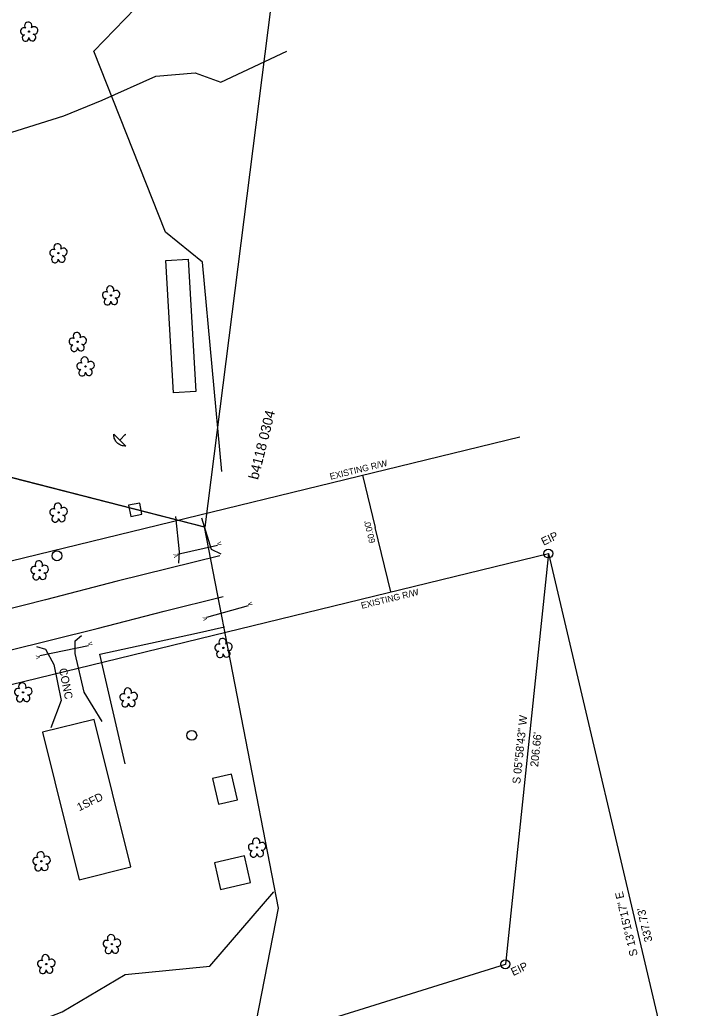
# Model space of a CAD drawing. Extents: x 1380524 to 1382335, y 594765 to 596944.
# Drawn here: x 1381991.4 to 1382333.2, y 595723.8 to 596218 of the extents above; entities that cross this region are included whole.
import ezdxf

# ---------------------------------------------------------------- set-up
doc = ezdxf.new("R2010")
doc.units = 0
for name, color, linetype in [('DTM Contours Major Text', 7, 'Continuous'), ('DTM Contours Minor', 7, 'Continuous'), ('Exist Other Culture Fence Line Text', 7, 'Continuous'), ('Exist Right of Way Line Text', 7, 'Continuous'), ('Exist Roads EOP', 7, 'Continuous'), ('Exist Structure Major Deck Tunnel Box Culvert', 7, 'Continuous'), ('Exist Utilities Power Tower CELL', 7, 'Continuous'), ('Exist Utilities Power Tower Text', 7, 'Continuous'), ('Exist Vertical Profile Vertical Axis Label', 7, 'Continuous'), ('Prop Approach Slab', 7, 'Continuous'), ('Prop Drainage Ditch Base Lines', 7, 'Continuous'), ('Prop Drainage Structure Box Number Symbol CELL', 7, 'Continuous'), ('Prop Drainage Structure Pipe CSP 15in', 7, 'Continuous'), ('Prop Drainage Structure Pipe Elbow CELL', 7, 'Continuous'), ('Prop Drainage Structure Pipe Elbow Label', 7, 'Continuous'), ('Prop Drainage Structure Plot Symbol 20 Scale CELL', 7, 'Continuous'), ('Prop Earthen Structure Cut Ditch Special Detail Label', 7, 'Continuous'), ('Prop Earthen Structure Ditch Flow Line', 7, 'Continuous'), ('Prop Earthen Structure V Ditch Lateral Detail Label', 7, 'Continuous'), ('Prop Erosion Rip Rap At Embankment Detail CELL', 7, 'Continuous'), ('Prop SS Transition Line', 7, 'Continuous')]:
    doc.layers.add(name, color=color, linetype=linetype)

# ---------------------------------------------------------------- blocks, each defined once
blk = doc.blocks.new('EXIST UTILITIES TV SATELLITE DISH')
at = {"layer": 'DTM Contours Minor'}
blk.add_line((0, 0), (0, 0), dxfattribs=at)
for points in [[(0.0605, -0.0604), (0.05, -0.0604), (0.0392, -0.0594), (0.0287, -0.0577), (0.0185, -0.0547), (0.0085, -0.0509), (-0.001, -0.0462), (-0.01, -0.0407), (-0.0185, -0.0344), (-0.0265, -0.0274), (-0.0335, -0.0194), (-0.0398, -0.0109), (-0.0453, -0.0019), (-0.05, 0.0076), (-0.0538, 0.0176), (-0.0568, 0.0278), (-0.0585, 0.0383), (-0.0595, 0.0491), (-0.0595, 0.0596)], [(-0.0595, 0.0596), (0.0605, -0.0604)], [(0, 0), (0.0585, 0.0575), (0.0578, 0.0585), (0.052, 0.0527), (0.0537, 0.051), (0.0595, 0.0568), (0.0585, 0.0575)]]:
    blk.add_lwpolyline(points, dxfattribs=at)
blk = doc.blocks.new('EXIST VEGETATION TREE')
at = {"layer": 'Prop Erosion Rip Rap At Embankment Detail CELL'}
blk.add_line((0, 0), (0, 0), dxfattribs=at)
blk.add_circle((0, 0), 0.00652, dxfattribs=at)
for centre, radius, start, end in [((-0.0521, 0.0031), 0.0345, 62.66361, 279.3457), ((-0.0077, 0.0575), 0.0371, 330.16508, 219.71335), ((0.051, 0.0118), 0.038, 257.1011, 134.19993), ((-0.0341, -0.0624), 0.0338, 111.56708, 6.23104), ((0.0335, -0.058), 0.034, 181.28216, 74.55999)]:
    blk.add_arc(centre, radius, start, end, dxfattribs=at)
blk = doc.blocks.new('EXIST UTILITIES OTHER POLE')
at = {"layer": 'DTM Contours Major Text'}
blk.add_circle((0, 0), 0.0493, dxfattribs=at)

msp = doc.modelspace()

# ---------------------------------------------------------------- linework, layer by layer
at = {"layer": 'Exist Roads EOP'}
for p, q in [((1381864.07, 595917.48), (1382241.54, 596009.42)), ((1381884.86, 595860.79), (1382255.74, 595951.12))]:
    msp.add_line(p, q, dxfattribs=at)
at = {"layer": 'Exist Utilities Power Tower CELL'}
for p in [(1382162.74, 595990.23), (1382176.94, 595931.93)]:
    msp.add_line(p, (1382169.1, 595964.11), dxfattribs=at)
at = {"layer": 'Exist Utilities Power Tower Text'}
for p, q in [((1382255.74, 595951.12), (1382234.24, 595745.79)), ((1382255.74, 595951.12), (1382333.18, 595622.39)), ((1381879.85, 595635.61), (1382234.24, 595745.79))]:
    msp.add_line(p, q, dxfattribs=at)
at = {"layer": 'Prop Drainage Ditch Base Lines'}
for points in [[(1382068.3, 596031.42), (1382064.41, 596097.65), (1382075.63, 596098.31), (1382079.52, 596032.08)], [(1382045.84, 595975.24), (1382046.98, 595969.67), (1382052.52, 595970.8), (1382051.39, 595976.37)], [(1382046.96, 595794.46), (1382028.61, 595868.21), (1382002.86, 595861.8), (1382021.2, 595788.04)], [(1382087.76, 595838.68), (1382090.75, 595825.76), (1382100.33, 595827.97), (1382097.34, 595840.89)], [(1382088.79, 595796.54), (1382091.87, 595783.18), (1382106.86, 595786.62), (1382103.78, 595799.99)]]:
    msp.add_lwpolyline(points, close=True, dxfattribs=at)
at = {"layer": 'Prop Drainage Structure Box Number Symbol CELL'}
for points in [[(1382083.99, 595964.39), (1380966.64, 596251.47), (1381106.82, 596554.99), (1381897.61, 596920.15), (1382148.43, 596473.2)], [(1382083.62, 595964.41), (1382120.69, 595773.82), (1382095.82, 595646.75), (1382010.85, 595488.75), (1381848.52, 595352.32), (1381617.36, 595239.15), (1381304.92, 595184.07), (1381005.77, 595330.75), (1380937.13, 595525.19), (1380768.47, 595849.39), (1380967, 596250.36)]]:
    msp.add_lwpolyline(points, close=True, dxfattribs=at)
at = {"layer": 'Prop Drainage Structure Pipe Elbow CELL'}
for points in [[(1382070.88, 595946.31), (1382071.32, 595952), (1382069.49, 595969.65)], [(1382082.26, 595969.02), (1382087.15, 595953.28), (1382091.88, 595950.93)]]:
    msp.add_lwpolyline(points, dxfattribs=at)
at = {"layer": 'Prop Drainage Structure Pipe Elbow Label'}
for points in [[(1382070.27, 595950.82), (1382090.33, 595955.31)], [(1382084.88, 595919.39), (1382105.79, 595925.1)], [(1382001.48, 595900.17), (1382025.79, 595905.24)]]:
    msp.add_lwpolyline(points, dxfattribs=at)
at = {"layer": 'Prop Drainage Structure Plot Symbol 20 Scale CELL'}
msp.add_line((1382091.96, 596186.73), (1382125, 596202.32), dxfattribs=at)
msp.add_lwpolyline([(1381903.65, 596138.7), (1381948.03, 596149.99), (1381984.23, 596160.72), (1382013.51, 596169.97), (1382032.7, 596177.77), (1382059.4, 596189.79), (1382079.06, 596191.47), (1382091.96, 596186.73)], dxfattribs=at)
at = {"layer": 'Prop Earthen Structure Cut Ditch Special Detail Label'}
for points in [[(1382092.39, 595992.13), (1382082.77, 596096.76), (1382064.27, 596111.84), (1382028.39, 596202.28), (1382090.44, 596266.51), (1382123.08, 596279.15), (1382074.65, 596322.1), (1382070.72, 596348.45), (1382135.72, 596332.26)], [(1382110.04, 595713.45), (1382067.83, 595699.67), (1381990.15, 595678.17), (1381936.17, 595661.06), (1381895.27, 595653.13), (1381895.13, 595667.26), (1381911.22, 595723.52), (1381948.84, 595697.3), (1382012.6, 595721.97), (1382044.15, 595740.68), (1382086.44, 595744.88), (1382118.43, 595781.95)]]:
    msp.add_lwpolyline(points, dxfattribs=at)
at = {"layer": 'Prop Earthen Structure Ditch Flow Line'}
for points in [[(1382091.45, 595950.01), (1382040.09, 595937.29), (1382004.26, 595928.01), (1381958.8, 595916.53), (1381926.33, 595908.18), (1381894.21, 595900.91), (1381876.52, 595897.14), (1381867, 595896.29), (1381860.37, 595897.28), (1381854.86, 595900.27), (1381851.95, 595903.63), (1381839.95, 595931.67), (1381826.08, 595965.16), (1381814.38, 595994.56), (1381803.44, 596023.95), (1381793.75, 596050.62), (1381789.17, 596063.13)], [(1381875.4, 595867.69), (1381880.08, 595872.41), (1381886.87, 595876.59), (1381895.15, 595879.13), (1381919.07, 595885.76), (1381948.74, 595893.46), (1381985.14, 595902.41), (1382030.18, 595913.69), (1382063.68, 595922.37), (1382093.15, 595929.66)], [(1382032.55, 595867.24), (1382023.57, 595881.83), (1382019.2, 595901.1), (1382019.18, 595907.44), (1382022.28, 595910.14)], [(1381999.85, 595904.61), (1382004.32, 595903.35), (1382008.52, 595895.69), (1382012.16, 595877.58), (1382007.03, 595863.97)]]:
    msp.add_lwpolyline(points, dxfattribs=at)
at = {"layer": 'Prop Earthen Structure V Ditch Lateral Detail Label'}
msp.add_lwpolyline([(1382044.11, 595845.95), (1382031.38, 595900.88), (1382079.86, 595911.36), (1382093.83, 595914.54)], dxfattribs=at)
at = {"layer": 'Prop SS Transition Line'}
for centre, radius in [((1382255.74, 595951.12), 2.2), ((1382255.74, 595951.12), 0.0707), ((1382234.24, 595745.79), 2.2), ((1382234.24, 595745.79), 0.0707)]:
    msp.add_circle(centre, radius, dxfattribs=at)

# ---------------------------------------------------------------- block references
at = {"layer": 'DTM Contours Major Text', "xscale": 50, "yscale": 50}
for p in [(1382010.03, 595949.99), (1382077.43, 595860.23)]:
    msp.add_blockref('EXIST UTILITIES OTHER POLE', p, dxfattribs=at)
at = {"layer": 'DTM Contours Minor', "xscale": 50, "yscale": 50}
msp.add_blockref('EXIST UTILITIES TV SATELLITE DISH', (1382041.38, 596007.88), dxfattribs=at)
at = {"layer": 'Prop Erosion Rip Rap At Embankment Detail CELL', "xscale": 50, "yscale": 50}
for p in [(1381996.03, 596212.04), (1382010.71, 596101.31), (1382037.02, 596080.18), (1382020.35, 596056.99), (1382024.27, 596044.67), (1382010.81, 595971.65), (1382001.32, 595942.76), (1382093.22, 595903.94), (1381993.1, 595881.74), (1382045.84, 595879.2), (1382110.02, 595804.17), (1382002.26, 595797.29), (1382037.45, 595755.9), (1382004.66, 595745.9)]:
    msp.add_blockref('EXIST VEGETATION TREE', p, dxfattribs=at)

# ---------------------------------------------------------------- texts
at = {"layer": 'Exist Other Culture Fence Line Text'}
for s, rotation, p in [('S 05%%D58\'43" W', 84.0215, (1382241.65, 595835.78)), ("206.66'", 84.0215, (1382250.59, 595844.31)), ('S 13%%D15\'17" E', 103.2548, (1382300.48, 595750.32)), ("337.73'", 103.2548, (1382307.83, 595757.44))]:
    msp.add_text(s, height=4, rotation=rotation, dxfattribs=at).set_placement(p)
at = {"layer": 'Exist Right of Way Line Text'}
for p in [(1382146.84, 595988), (1382162.5, 595923.47)]:
    msp.add_text('EXISTING R/W', height=3.2, rotation=13.6882, dxfattribs=at).set_placement(p)
at = {"layer": 'Exist Structure Major Deck Tunnel Box Culvert'}
for p in [(1382253.3, 595955.01), (1382238.17, 595739.87)]:
    msp.add_text('EIP', height=4, rotation=25.2286, dxfattribs=at).set_placement(p)
at = {"layer": 'Exist Utilities Power Tower CELL'}
msp.add_text("60.00'", height=3.2, rotation=103.6882, dxfattribs=at).set_placement((1382169.33, 595956.73))
at = {"layer": 'Exist Vertical Profile Vertical Axis Label'}
msp.add_text('CONC', height=4, rotation=281.3699, dxfattribs=at).set_placement((1382011.01, 595893.45))
at = {"layer": 'Prop Approach Slab'}
msp.add_text('1SFD', height=4, rotation=25.7848, dxfattribs=at).set_placement((1382021.2, 595822.25))
at = {"layer": 'Prop Drainage Structure Pipe CSP 15in'}
msp.add_text('b4118 0304', height=5, rotation=75.9302, dxfattribs=at).set_placement((1382110.61, 595987.75))
at = {"layer": 'Prop Drainage Structure Pipe Elbow Label'}
for rotation, p in [(282.8664, (1382089.99, 595956.78)), (102.3847, (1382070.59, 595949.35)), (285.494, (1382105.39, 595926.54)), (105.0123, (1382085.27, 595917.94)), (282.0166, (1382025.48, 595906.71)), (101.5349, (1382001.78, 595898.7))]:
    msp.add_text('v', height=2.65, rotation=rotation, dxfattribs=at).set_placement(p)

doc.saveas('drawing.dxf')
